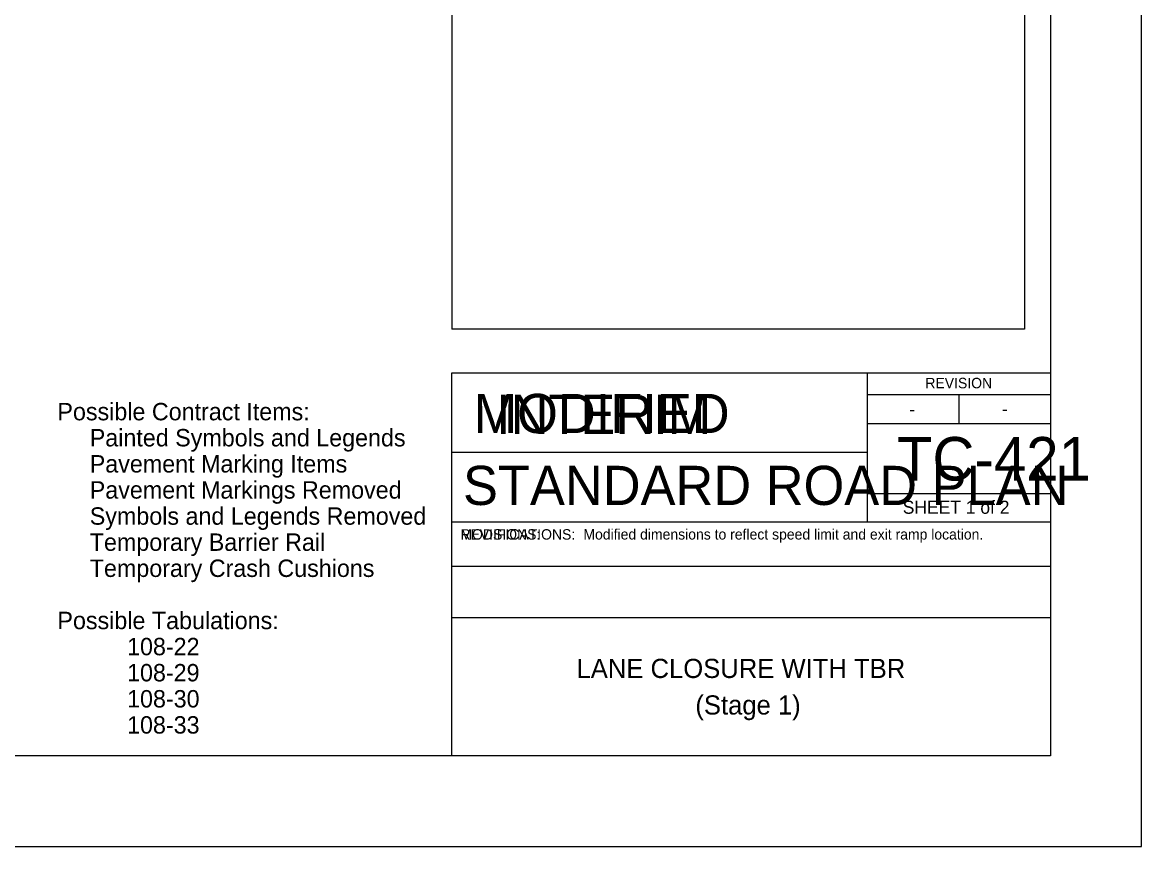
# Model space of a CAD drawing. Extents: x 10133 to 81668, y 4177 to 11018.
# Drawn here: x 26486 to 27772, y 7820 to 8767 of the extents above; entities that cross this region are included whole.
import ezdxf

# ---------------------------------------------------------------- set-up
doc = ezdxf.new("R2010")
doc.units = 0
for name, color, linetype in [('dsnShtPlotShapeBatchPrint', 7, 'Continuous'), ('dsnStdBlockModified', 7, 'Continuous'), ('dsnStdBorder', 7, 'Continuous'), ('Level 1', 7, 'Continuous'), ('SheetBorder', 7, 'Continuous'), ('StdDetailLabel', 7, 'Continuous'), ('StdDimension', 7, 'Continuous'), ('StdNote', 7, 'Continuous'), ('StdNoteLinks', 7, 'Continuous')]:
    doc.layers.add(name, color=color, linetype=linetype)

msp = doc.modelspace()

# ---------------------------------------------------------------- linework, layer by layer
at = {"layer": 'dsnShtPlotShapeBatchPrint'}
for p, q in [((26979.5, 9884), (26979.5, 8414)), ((27637.5, 9884), (27637.5, 8414)), ((27637.5, 8414), (26979.5, 8414))]:
    msp.add_line(p, q, dxfattribs=at)
at = {"layer": 'dsnStdBlockModified'}
msp.add_lwpolyline([(24532.5, 9934), (27667.5, 9934), (27667.5, 7924), (24532.5, 7924)], close=True, dxfattribs=at)
at = {"layer": 'dsnStdBorder'}
msp.add_lwpolyline([(24428, 7819.5), (27772, 7819.5), (27772, 10403.5), (24428, 10403.5)], close=True, dxfattribs=at)
at = {"layer": 'SheetBorder'}
msp.add_lwpolyline([(24532.5, 9944), (27667.5, 9944), (27667.5, 7924), (24532.5, 7924)], close=True, dxfattribs=at)
at = {"layer": 'StdNoteLinks'}
for p, q in [((27456.6, 8364), (27456.6, 8272.7)), ((27456.6, 8339.1), (27667.5, 8339.1)), ((27562.1, 8339.1), (27562.1, 8305.9)), ((27456.6, 8305.9), (27667.5, 8305.9)), ((26979.5, 8272.7), (27456.6, 8272.7)), ((27456.6, 8272.7), (27456.6, 8192.7)), ((27667.5, 8224.9), (27456.6, 8224.9)), ((26979.5, 8192.7), (27667.5, 8192.7)), ((26979.5, 8141.7), (27667.5, 8141.7)), ((26979.5, 8082.7), (27667.5, 8082.7))]:
    msp.add_line(p, q, dxfattribs=at)
msp.add_lwpolyline([(26979.5, 8364), (27667.5, 8364), (27667.5, 7924), (26979.5, 7924)], close=True, dxfattribs=at)

# ---------------------------------------------------------------- texts
at = {"layer": 'Level 1'}
for s, p in [('Possible Contract Items:', (26526.6, 8309.4)), ('     Painted Symbols and Legends', (26526.6, 8279.4)), ('     Pavement Marking Items', (26526.6, 8249.4)), ('     Pavement Markings Removed', (26526.6, 8219.4)), ('     Symbols and Legends Removed', (26526.6, 8189.4)), ('     Temporary Barrier Rail', (26526.6, 8159.4)), ('     Temporary Crash Cushions', (26526.6, 8129.4)), ('Possible Tabulations:', (26526.6, 8069.4)), ('108-22', (26606.6, 8039.4)), ('108-29', (26606.6, 8009.4)), ('108-30', (26606.6, 7979.4)), ('108-33', (26606.6, 7949.4))]:
    msp.add_text(s, height=20, dxfattribs=at).set_placement(p)
at = {"layer": 'StdDetailLabel'}
msp.add_text('INTERIM', height=45, dxfattribs=at).set_placement((27030.5, 8293.7))
at = {"layer": 'StdDimension'}
for s, height, p in [('MODIFIED', 45, (27004.6, 8294.8)), ('MODIFICATIONS:', 12, (26989.5, 8172.3))]:
    msp.add_text(s, height=height, dxfattribs=at).set_placement(p)
at = {"layer": 'StdNote'}
msp.add_text('REVISIONS:', height=12, dxfattribs=at).set_placement((26989.5, 8172.3))
at = {"layer": 'StdNoteLinks'}
for s, height, p in [('REVISION', 12, (27523.6, 8346.2)), ('-', 15, (27505.1, 8314.7)), ('-', 15, (27611.6, 8315.1)), ('TC-421', 50, (27490.9, 8240.2)), ('STANDARD ROAD PLAN', 45.001, (26992.5, 8212.1)), ('SHEET 1 of 2', 15, (27497.6, 8202)), ('Modified dimensions to reflect speed limit and exit ramp location.', 12, (27130.8, 8172.4)), ('LANE CLOSURE WITH TBR', 22, (27122.9, 8013.3)), ('(Stage 1)', 22, (27259.4, 7971.3))]:
    msp.add_text(s, height=height, dxfattribs=at).set_placement(p)

doc.saveas('drawing.dxf')
